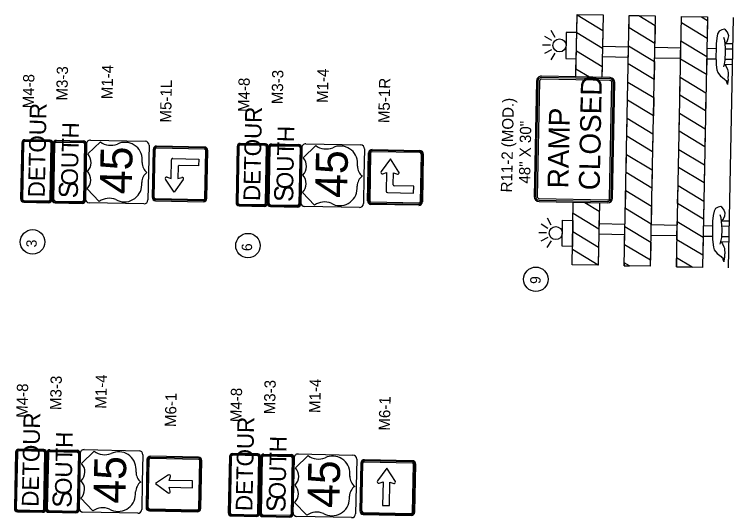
# Model space of a CAD drawing. Extents: x 335726 to 369746, y 119154 to 200788.
# Drawn here: x 339293 to 349629, y 178618 to 185853 of the extents above; entities that cross this region are included whole.
import ezdxf

# ---------------------------------------------------------------- set-up
doc = ezdxf.new("R2010")
doc.units = 0
doc.layers.add('CA-TEXT', color=7, linetype='Continuous')
doc.layers.add('P_SGN_Cell', color=7, linetype='Continuous')

msp = doc.modelspace()

# ---------------------------------------------------------------- linework, layer by layer
at = {"layer": 'CA-TEXT'}
for centre in [(339554, 182582), (342650, 182529), (346787, 182044)]:
    msp.add_circle(centre, 176, dxfattribs=at)
at = {"layer": 'P_SGN_Cell'}
for p, q in [((349557, 182209), (349629, 185808)), ((347015, 185476), (346918, 185535)), ((347064, 185523), (347009, 185622)), ((349506, 185436), (349622, 185433)), ((346996, 185411), (346883, 185413)), ((347012, 185345), (346913, 185291)), ((347746, 185396), (348120, 185388)), ((348495, 185381), (348870, 185373)), ((349245, 185366), (349378, 185363)), ((349511, 185360), (349620, 185358)), ((347059, 185296), (347001, 185200)), ((347743, 185246), (348117, 185238)), ((348492, 185231), (348867, 185223)), ((349242, 185216), (349375, 185213)), ((349497, 185136), (349616, 185133)), ((349510, 185210), (349617, 185208)), ((347853, 184902), (346868, 184922)), ((347854, 184944), (346869, 184964)), ((347853, 184925), (346869, 184945)), ((346798, 184895), (346764, 183235)), ((346816, 184895), (346783, 183235)), ((346840, 184894), (346806, 183235)), ((347847, 183214), (347881, 184873)), ((347871, 183213), (347904, 184873)), ((347889, 183213), (347923, 184872)), ((339833, 183189), (339849, 184000)), ((339844, 183190), (339860, 184000)), ((339859, 183189), (339875, 183999)), ((339894, 184018), (340284, 184010)), ((339895, 184044), (340285, 184036)), ((339895, 184033), (340285, 184025)), ((340303, 183991), (340286, 183181)), ((340318, 183990), (340301, 183181)), ((340329, 183990), (340313, 183180)), ((340313, 183203), (340329, 183990)), ((340529, 184021), (340347, 183846)), ((340386, 184045), (341174, 184029)), ((342990, 183991), (343380, 183983)), ((343481, 183992), (344269, 183976)), ((341229, 183972), (341221, 183578)), ((341229, 183972), (341229, 183972)), ((341286, 183912), (341273, 183223)), ((341286, 183223), (341300, 183912)), ((341302, 183222), (341316, 183911)), ((342025, 183933), (341336, 183947)), ((342025, 183917), (341336, 183930)), ((342026, 183946), (341337, 183960)), ((342030, 183208), (342044, 183897)), ((342047, 183207), (342061, 183896)), ((342060, 183207), (342074, 183896)), ((342928, 183136), (342944, 183947)), ((342939, 183137), (342955, 183947)), ((342954, 183136), (342970, 183946)), ((342989, 183965), (343379, 183957)), ((342990, 183980), (343380, 183972)), ((343398, 183938), (343381, 183128)), ((343413, 183937), (343396, 183128)), ((343424, 183937), (343408, 183127)), ((343408, 183150), (343424, 183937)), ((343624, 183968), (343442, 183793)), ((344324, 183919), (344316, 183525)), ((344324, 183919), (344324, 183919)), ((344433, 183909), (345122, 183895)), ((345122, 183882), (344433, 183896)), ((341569, 183781), (341943, 183774)), ((344369, 183172), (344383, 183861)), ((344396, 183861), (344382, 183172)), ((344412, 183860), (344399, 183171)), ((345121, 183866), (344433, 183879)), ((345141, 183846), (345127, 183157)), ((345157, 183845), (345143, 183156)), ((345170, 183845), (345156, 183156)), ((341130, 183723), (341131, 183759)), ((341544, 183495), (341549, 183762)), ((341941, 183675), (341662, 183681)), ((341943, 183774), (341941, 183675)), ((344226, 183670), (344226, 183706)), ((344696, 183776), (344565, 183593)), ((344820, 183587), (344696, 183776)), ((341221, 183578), (341213, 183185)), ((341646, 183665), (341642, 183493)), ((344586, 183562), (344643, 183578)), ((344643, 183578), (344638, 183311)), ((344738, 183404), (344742, 183576)), ((344742, 183576), (344798, 183558)), ((341589, 183295), (341465, 183484)), ((341488, 183513), (341544, 183495)), ((341721, 183478), (341589, 183295)), ((341642, 183493), (341699, 183509)), ((344316, 183525), (344308, 183132)), ((341124, 183402), (341125, 183437)), ((344219, 183349), (344220, 183384)), ((345033, 183382), (344754, 183387)), ((345031, 183283), (345033, 183382)), ((340337, 183346), (340512, 183164)), ((343432, 183293), (343607, 183111)), ((344657, 183291), (345031, 183283)), ((339877, 183170), (340267, 183162)), ((342010, 183188), (341321, 183202)), ((342010, 183172), (341321, 183186)), ((341321, 183173), (342010, 183159)), ((346833, 183182), (347818, 183163)), ((346833, 183164), (347818, 183144)), ((346834, 183206), (347818, 183186)), ((339877, 183155), (340267, 183147)), ((339877, 183144), (340267, 183136)), ((341155, 183130), (340368, 183145)), ((342972, 183117), (343362, 183109)), ((342972, 183102), (343362, 183094)), ((342972, 183091), (343362, 183083)), ((344251, 183077), (343463, 183092)), ((345106, 183108), (344417, 183122)), ((345107, 183137), (344418, 183151)), ((345106, 183121), (344418, 183135)), ((347009, 182824), (346955, 182923)), ((347694, 182847), (348069, 182839)), ((349454, 182886), (349570, 182884)), ((346960, 182777), (346864, 182835)), ((348444, 182831), (348819, 182824)), ((349194, 182816), (349323, 182814)), ((349461, 182811), (349569, 182809)), ((346941, 182712), (346829, 182714)), ((346958, 182646), (346859, 182591)), ((347691, 182697), (348066, 182689)), ((348441, 182681), (348816, 182674)), ((349191, 182666), (349323, 182664)), ((349458, 182661), (349566, 182659)), ((347005, 182597), (346946, 182500)), ((349446, 182586), (349564, 182584)), ((339743, 178739), (339759, 179550)), ((339754, 178740), (339771, 179550)), ((339769, 178739), (339786, 179549)), ((339805, 179594), (340195, 179586)), ((339805, 179583), (340195, 179575)), ((339805, 179568), (340195, 179560)), ((340213, 179541), (340197, 178731)), ((340228, 179540), (340212, 178731)), ((340239, 179540), (340223, 178730)), ((340223, 178753), (340239, 179540)), ((340439, 179571), (340257, 179396)), ((340297, 179595), (341084, 179579)), ((341139, 179522), (341131, 179128)), ((341139, 179522), (341139, 179522)), ((341198, 179454), (341185, 178765)), ((341198, 178765), (341212, 179454)), ((341214, 178764), (341228, 179453)), ((341248, 179489), (341937, 179475)), ((341248, 179473), (341937, 179459)), ((341938, 179488), (341249, 179502)), ((341942, 178750), (341956, 179439)), ((341959, 178749), (341973, 179438)), ((341972, 178749), (341986, 179438)), ((342817, 178677), (342834, 179488)), ((342829, 178678), (342845, 179488)), ((342844, 178678), (342860, 179487)), ((342879, 179532), (343269, 179524)), ((342879, 179521), (343269, 179513)), ((342879, 179506), (343269, 179498)), ((343287, 179479), (343271, 178669)), ((343302, 179478), (343286, 178669)), ((343313, 179478), (343297, 178668)), ((343298, 178691), (343313, 179478)), ((343514, 179509), (343332, 179334)), ((343371, 179533), (344158, 179517)), ((344213, 179460), (344205, 179066)), ((344213, 179460), (344213, 179460)), ((344322, 179437), (345011, 179423)), ((345012, 179436), (344323, 179450)), ((344272, 179402), (344259, 178713)), ((344272, 178713), (344286, 179402)), ((344288, 178712), (344302, 179401)), ((344322, 179421), (345011, 179407)), ((345016, 178698), (345030, 179387)), ((345033, 178697), (345047, 179386)), ((345046, 178697), (345060, 179386)), ((341041, 179273), (341042, 179309)), ((341508, 179231), (341320, 179107)), ((344115, 179211), (344116, 179247)), ((344644, 179328), (344512, 179145)), ((344768, 179139), (344644, 179328)), ((341131, 179128), (341123, 178735)), ((341519, 179152), (341537, 179208)), ((341855, 179145), (341519, 179152)), ((341853, 179047), (341855, 179145)), ((344534, 179114), (344591, 179130)), ((344591, 179130), (344584, 178794)), ((344682, 178792), (344689, 179128)), ((344689, 179128), (344745, 179110)), ((341320, 179107), (341503, 178975)), ((341533, 178997), (341517, 179054)), ((341517, 179054), (341853, 179047)), ((344205, 179066), (344197, 178673)), ((341034, 178952), (341035, 178987)), ((344109, 178890), (344109, 178925)), ((340247, 178896), (340422, 178714)), ((343321, 178834), (343496, 178652)), ((339788, 178720), (340178, 178712)), ((341233, 178744), (341922, 178730)), ((341233, 178728), (341922, 178714)), ((341233, 178715), (341922, 178701)), ((344584, 178794), (344682, 178792)), ((339787, 178705), (340177, 178697)), ((339787, 178694), (340177, 178686)), ((341066, 178680), (340278, 178695)), ((342861, 178632), (343251, 178624)), ((342862, 178658), (343252, 178651)), ((342862, 178643), (343251, 178636)), ((344140, 178618), (343353, 178634)), ((344307, 178692), (344996, 178678)), ((344307, 178676), (344996, 178662)), ((344307, 178663), (344996, 178649))]:
    msp.add_line(p, q, dxfattribs=at)
for points in [[(347362, 184954), (347380, 185853), (347755, 185846), (347737, 184946)], [(349510, 185443), (349538, 185463), (349552, 185507), (349560, 185545), (349540, 185597), (349514, 185631), (349498, 185642), (349459, 185632), (349422, 185613), (349400, 185572), (349386, 185511), (349379, 185429), (349378, 185353), (349376, 185250), (349379, 185168), (349380, 185127), (349390, 185055), (349403, 185017), (349443, 184965), (349463, 184951), (349504, 184919), (349513, 184909), (349540, 184891)], [(349497, 185138), (349509, 185196), (349514, 185313), (349513, 185371), (349501, 185477), (349488, 185519)], [(347559, 184950), (347364, 185068), (347369, 185328), (347740, 185104), (347737, 184946)], [(349489, 185098), (349497, 185137)], [(349508, 185128), (349521, 185104), (349541, 185062), (349547, 185042), (349549, 185011), (349553, 184980), (349553, 184963), (349548, 184952), (349551, 184901), (349547, 184901), (349544, 184891), (349539, 184847)], [(347737, 184946), (347362, 184954)], [(347737, 184946), (347559, 184950)], [(339399, 184008), (339383, 183198)], [(339410, 184008), (339394, 183198)], [(339425, 184008), (339409, 183198)], [(339804, 184019), (339444, 184026)], [(339805, 184045), (339445, 184052)], [(339805, 184034), (339445, 184041)], [(339806, 183190), (339823, 184000)], [(339821, 183190), (339838, 183999)], [(339833, 183189), (339849, 183999)], [(342900, 183992), (342540, 183999)], [(342900, 183981), (342540, 183988)], [(342494, 183955), (342478, 183145)], [(342505, 183955), (342489, 183145)], [(342520, 183955), (342504, 183145)], [(342899, 183966), (342540, 183973)], [(342902, 183137), (342918, 183947)], [(342917, 183137), (342933, 183946)], [(342928, 183136), (342944, 183946)], [(339427, 183179), (339787, 183172)], [(339427, 183164), (339787, 183157)], [(339427, 183153), (339787, 183145)], [(342522, 183126), (342882, 183119)], [(342522, 183111), (342882, 183104)], [(342522, 183100), (342882, 183092)], [(347700, 183146), (347682, 182247), (347307, 182254), (347325, 183154)], [(347492, 183150), (347698, 183026), (347693, 182766), (347322, 182990), (347325, 183154)], [(347325, 183154), (347700, 183146)], [(347325, 183154), (347492, 183150)], [(349458, 182894), (349486, 182914), (349501, 182958), (349508, 182995), (349489, 183047), (349462, 183082), (349446, 183092), (349407, 183083), (349370, 183063), (349349, 183022), (349334, 182961), (349328, 182879), (349326, 182804), (349324, 182701), (349327, 182619), (349329, 182578), (349339, 182506), (349352, 182468), (349392, 182415), (349412, 182401), (349452, 182370), (349461, 182359), (349488, 182342)], [(349446, 182589), (349458, 182647), (349463, 182763), (349461, 182822), (349450, 182928), (349437, 182969)], [(349438, 182548), (349446, 182587)], [(349457, 182578), (349470, 182554), (349490, 182513), (349496, 182492), (349498, 182461), (349502, 182430), (349501, 182413), (349496, 182403), (349500, 182352), (349495, 182352), (349493, 182341), (349487, 182297)], [(339309, 179558), (339293, 178748)], [(339321, 179558), (339304, 178748)], [(339336, 179558), (339319, 178748)], [(339715, 179595), (339355, 179602)], [(339715, 179584), (339355, 179591)], [(339715, 179569), (339355, 179576)], [(339717, 178740), (339733, 179550)], [(339732, 178740), (339748, 179549)], [(339743, 178739), (339759, 179549)], [(342789, 179533), (342430, 179540)], [(342384, 179496), (342367, 178687)], [(342395, 179496), (342379, 178686)], [(342410, 179496), (342394, 178686)], [(342789, 179522), (342429, 179529)], [(342789, 179507), (342429, 179514)], [(342791, 178678), (342807, 179488)], [(342806, 178678), (342822, 179488)], [(342817, 178677), (342834, 179487)], [(339337, 178714), (339697, 178707)], [(339338, 178729), (339698, 178722)], [(339337, 178703), (339697, 178695)], [(342411, 178641), (342771, 178633)], [(342412, 178667), (342772, 178660)], [(342412, 178652), (342772, 178645)]]:
    msp.add_lwpolyline(points, dxfattribs=at)
for points in [[(347745, 185364), (347374, 185588), (347380, 185847), (347750, 185623)], [(348057, 182239), (348130, 185838), (348504, 185831), (348432, 182232)], [(348497, 185435), (348126, 185659), (348130, 185838), (348269, 185836), (348502, 185695)], [(348807, 182224), (348879, 185823), (349254, 185816), (349182, 182216)], [(349253, 185766), (349248, 185507), (348878, 185731), (348879, 185823), (349169, 185817)], [(347224, 185594), (347217, 185219), (347367, 185216), (347374, 185591)], [(349238, 184987), (348867, 185211), (348872, 185471), (349243, 185247)], [(348486, 184916), (348115, 185140), (348121, 185399), (348491, 185175)], [(349227, 184468), (348857, 184692), (348862, 184951), (349232, 184727)], [(348476, 184396), (348105, 184620), (348110, 184880), (348481, 184656)], [(349217, 183948), (348846, 184172), (348851, 184432), (349222, 184208)], [(348465, 183877), (348095, 184101), (348100, 184360), (348470, 184136)], [(349206, 183429), (348836, 183653), (348841, 183912), (349211, 183688)], [(348455, 183357), (348084, 183581), (348089, 183841), (348460, 183617)], [(349196, 182909), (348825, 183133), (348830, 183393), (349201, 183169)], [(348444, 182838), (348074, 183062), (348079, 183321), (348449, 183097)], [(347163, 182520), (347170, 182895), (347320, 182892), (347312, 182517)], [(349185, 182390), (348815, 182614), (348820, 182873), (349191, 182649)], [(348434, 182318), (348063, 182542), (348068, 182802), (348439, 182578)], [(347682, 182247), (347312, 182471), (347317, 182730), (347687, 182506)], [(348810, 182354), (348807, 182224), (349032, 182219)], [(348058, 182282), (348057, 182239), (348132, 182238)]]:
    msp.add_lwpolyline(points, close=True, dxfattribs=at)
for centre in [(347127, 185408), (347073, 182709)]:
    msp.add_circle(centre, 93.8, dxfattribs=at)
for centre, radius, start, end in [((346868, 184894), 70.3, 88.8462, 178.8462), ((346868, 184894), 51.6, 88.8462, 178.8462), ((346868, 184894), 28.1, 88.8462, 178.8462), ((347852, 184874), 51.6, 358.8462, 88.8462), ((347852, 184874), 70.3, 358.8462, 88.8462), ((347852, 184874), 28.1, 358.8462, 88.8462), ((339444, 184007), 45, 88.8468, 178.8468), ((339444, 184007), 33.7, 88.8468, 178.8468), ((339444, 184007), 18.7, 88.8468, 178.8468), ((339804, 184000), 18.7, 358.8468, 88.8468), ((339804, 184000), 45, 358.8468, 88.8468), ((339804, 184000), 33.7, 358.8468, 88.8468), ((339894, 183999), 45, 88.8462, 178.8462), ((339894, 183999), 33.7, 88.8462, 178.8462), ((339894, 183999), 18.7, 88.8462, 178.8462), ((340284, 183991), 18.7, 358.8462, 88.8462), ((340284, 183991), 45, 358.8462, 88.8462), ((340284, 183991), 33.7, 358.8462, 88.8462), ((340385, 183989), 56.2, 88.8462, 178.8462), ((340679, 184221), 250, 233.1143, 291.9873), ((340881, 183764), 250, 358.8462, 115.6928), ((341172, 183973), 56.2, 358.8462, 88.8462), ((342539, 183954), 45, 88.8468, 178.8468), ((342539, 183954), 33.7, 88.8468, 178.8468), ((342899, 183947), 45, 358.8468, 88.8468), ((342989, 183946), 45, 88.8462, 178.8462), ((343480, 183936), 56.2, 88.8462, 178.8462), ((341336, 183911), 49.2, 88.8462, 178.8462), ((341336, 183911), 36.1, 88.8462, 178.8462), ((341336, 183911), 19.7, 88.8462, 178.8462), ((342025, 183897), 36.1, 358.8462, 88.8462), ((342025, 183897), 19.7, 358.8462, 88.8462), ((342025, 183897), 49.2, 358.8462, 88.8462), ((342539, 183954), 18.7, 88.8468, 178.8468), ((342899, 183947), 18.7, 358.8468, 88.8468), ((342899, 183947), 33.7, 358.8468, 88.8468), ((342989, 183946), 33.7, 88.8462, 178.8462), ((342989, 183946), 18.7, 88.8462, 178.8462), ((343379, 183938), 18.7, 358.8462, 88.8462), ((343379, 183938), 45, 358.8462, 88.8462), ((343379, 183938), 33.7, 358.8462, 88.8462), ((343774, 184168), 250, 233.1143, 291.9873), ((343976, 183711), 250, 358.8462, 115.6928), ((344268, 183920), 56.2, 358.8462, 88.8462), ((344432, 183860), 49.2, 88.8462, 178.8462), ((344432, 183860), 36.1, 88.8462, 178.8462), ((345121, 183846), 49.2, 358.8462, 88.8462), ((345121, 183846), 36.1, 358.8462, 88.8462), ((340217, 183724), 179, 314.4191, 43.2734), ((341569, 183762), 19.7, 88.8462, 178.8462), ((343312, 183671), 179, 314.4191, 43.2734), ((344432, 183860), 19.7, 88.8462, 178.8462), ((345121, 183846), 19.7, 358.8462, 88.8462), ((341311, 183721), 181, 179.1885, 231.634), ((341662, 183665), 16.4, 88.8462, 178.8462), ((340212, 183474), 179, 314.4191, 43.2734), ((341305, 183433), 181, 126.0584, 178.5039), ((344406, 183668), 181, 179.1885, 231.634), ((344581, 183581), 19.7, 144.3166, 285.6488), ((344804, 183577), 19.7, 252.0436, 33.3759), ((341481, 183494), 19.7, 72.0436, 213.3759), ((341705, 183490), 19.7, 324.3166, 105.6488), ((343307, 183421), 179, 314.4191, 43.2734), ((344400, 183380), 181, 126.0584, 178.5039), ((340874, 183407), 250, 240.0981, 358.8463), ((344754, 183404), 16.4, 178.8462, 268.8462), ((343969, 183354), 250, 240.0981, 358.8463), ((344657, 183310), 19.7, 178.8462, 268.8462), ((339428, 183198), 45, 178.8468, 268.8468), ((339428, 183198), 33.7, 178.8468, 268.8468), ((339428, 183198), 18.7, 178.8468, 268.8468), ((339428, 183198), 18.7, 178.8468, 186.1883), ((339788, 183190), 33.7, 268.8468, 358.8468), ((339788, 183190), 18.7, 268.8468, 358.8468), ((339788, 183190), 45, 268.8468, 358.8468), ((339878, 183189), 45, 179.6119, 268.8462), ((339878, 183189), 33.7, 178.8462, 268.8462), ((339878, 183189), 18.7, 178.8462, 268.8462), ((340268, 183181), 33.7, 268.8462, 358.8462), ((340268, 183181), 18.7, 268.8462, 358.8462), ((340268, 183181), 45, 268.8462, 358.8462), ((340369, 183202), 56.2, 178.8462, 268.8462), ((340655, 182959), 250, 67.7159, 124.7982), ((341157, 183186), 56.2, 268.8462, 358.8462), ((341322, 183222), 49.2, 178.8462, 268.8462), ((341322, 183222), 36.1, 178.8462, 268.8462), ((341322, 183222), 19.7, 178.8462, 268.8462), ((342011, 183208), 19.7, 268.8462, 358.8462), ((342011, 183208), 36.1, 268.8462, 358.8462), ((342011, 183208), 49.2, 268.8462, 358.8462), ((344418, 183171), 49.2, 178.8462, 268.8462), ((344418, 183171), 36.1, 178.8462, 268.8462), ((344418, 183171), 19.7, 178.8462, 268.8462), ((345107, 183157), 19.7, 268.8462, 358.8462), ((346834, 183234), 70.3, 178.8462, 268.8462), ((346834, 183234), 51.6, 178.8462, 268.8462), ((346834, 183234), 28.1, 178.8462, 269.9241), ((347819, 183214), 28.1, 268.8462, 358.8462), ((347819, 183214), 70.3, 268.8462, 358.8462), ((347819, 183214), 51.6, 268.8462, 358.8462), ((342523, 183145), 45, 178.8468, 268.8468), ((342523, 183145), 33.7, 178.8468, 268.8468), ((342523, 183145), 18.7, 178.8468, 268.8468), ((342523, 183145), 18.7, 178.8468, 186.1883), ((342883, 183137), 33.7, 268.8468, 358.8468), ((342883, 183137), 18.7, 268.8468, 358.8468), ((342883, 183137), 45, 268.8468, 358.8468), ((342973, 183136), 45, 179.6119, 268.8462), ((342973, 183136), 33.7, 178.8462, 268.8462), ((342973, 183136), 18.7, 178.8462, 268.8462), ((343363, 183128), 33.7, 268.8462, 358.8462), ((343363, 183128), 18.7, 268.8462, 358.8462), ((343363, 183128), 45, 268.8462, 358.8462), ((343464, 183149), 56.2, 178.8462, 268.8462), ((343750, 182906), 250, 67.7159, 124.7982), ((344252, 183133), 56.2, 268.8462, 358.8462), ((345107, 183157), 36.1, 268.8462, 358.8462), ((345107, 183157), 49.2, 268.8462, 358.8462), ((339354, 179557), 45, 88.8468, 178.8468), ((339354, 179557), 33.7, 88.8468, 178.8468), ((339354, 179557), 18.7, 88.8468, 178.8468), ((339714, 179550), 45, 358.8468, 88.8468), ((339714, 179550), 33.7, 358.8468, 88.8468), ((339714, 179550), 18.7, 358.8468, 88.8468), ((339804, 179549), 45, 88.8462, 178.8462), ((339804, 179549), 33.7, 88.8462, 178.8462), ((339804, 179549), 18.7, 88.8462, 178.8462), ((340194, 179541), 45, 358.8462, 88.8462), ((340194, 179541), 33.7, 358.8462, 88.8462), ((340194, 179541), 18.7, 358.8462, 88.8462), ((340295, 179539), 56.2, 88.8462, 178.8462), ((340590, 179771), 250, 233.1143, 291.9873), ((340792, 179314), 250, 358.8462, 115.6928), ((341083, 179523), 56.2, 358.8462, 88.8462), ((342429, 179495), 45, 88.8468, 178.8468), ((341248, 179453), 49.2, 88.8468, 178.8468), ((341248, 179453), 49.2, 149.4503, 178.8468), ((341248, 179453), 36.1, 88.8468, 178.8468), ((341248, 179453), 19.7, 88.8468, 178.8468), ((341937, 179439), 36.1, 358.8468, 88.8468), ((341937, 179439), 19.7, 358.8468, 88.8468), ((341937, 179439), 49.2, 358.8468, 88.8468), ((342429, 179495), 33.7, 88.8468, 178.8468), ((342429, 179495), 18.7, 88.8468, 178.8468), ((342789, 179488), 45, 358.8468, 88.8468), ((342789, 179488), 33.7, 358.8468, 88.8468), ((342789, 179488), 18.7, 358.8468, 88.8468), ((342879, 179487), 45, 88.8462, 178.8462), ((342879, 179487), 33.7, 88.8462, 178.8462), ((342879, 179487), 18.7, 88.8462, 178.8462), ((343268, 179479), 45, 358.8462, 88.8462), ((343268, 179479), 33.7, 358.8462, 88.8462), ((343268, 179479), 18.7, 358.8462, 88.8462), ((343370, 179477), 56.2, 88.8462, 178.8462), ((343664, 179709), 250, 233.1143, 291.9873), ((343866, 179252), 250, 358.8462, 115.6928), ((344157, 179461), 56.2, 358.8462, 88.8462), ((344322, 179401), 49.2, 88.8468, 178.8468), ((344322, 179401), 36.1, 88.8468, 178.8468), ((345011, 179387), 49.2, 358.8468, 88.8468), ((340127, 179274), 179, 314.4191, 43.2734), ((343201, 179212), 179, 314.4191, 43.2734), ((344322, 179401), 49.2, 149.4503, 178.8468), ((344322, 179401), 19.7, 88.8468, 178.8468), ((345011, 179387), 36.1, 358.8468, 88.8468), ((345011, 179387), 19.7, 358.8468, 88.8468), ((341222, 179271), 181, 179.1885, 231.634), ((341519, 179214), 19.7, 342.0442, 123.3765), ((340122, 179024), 179, 314.4191, 43.2734), ((341216, 178983), 181, 126.0584, 178.5039), ((344296, 179209), 181, 179.1885, 231.634), ((344528, 179133), 19.7, 144.3172, 285.6494), ((344751, 179129), 19.7, 252.0442, 33.3765), ((343196, 178962), 179, 314.4191, 43.2734), ((344290, 178921), 181, 126.0584, 178.5039), ((340784, 178957), 250, 240.0981, 358.8463), ((341514, 178991), 19.7, 234.3172, 15.6494), ((343859, 178895), 250, 240.0981, 358.8463), ((339338, 178748), 45, 178.8468, 268.8468), ((339338, 178748), 33.7, 178.8468, 268.8468), ((339338, 178748), 18.7, 178.8468, 268.8468), ((339338, 178748), 18.7, 178.8468, 186.1883), ((339698, 178740), 33.7, 268.8468, 358.8468), ((339698, 178740), 45, 268.8468, 358.8468), ((339698, 178740), 18.7, 268.8468, 358.8468), ((339788, 178739), 45, 179.6119, 268.8462), ((339788, 178739), 33.7, 178.8462, 268.8462), ((339788, 178739), 18.7, 178.8462, 268.8462), ((340178, 178731), 33.7, 268.8462, 358.8462), ((340178, 178731), 45, 268.8462, 358.8462), ((340178, 178731), 18.7, 268.8462, 358.8462), ((340280, 178752), 56.2, 178.8462, 268.8462), ((340565, 178509), 250, 67.7159, 124.7982), ((341067, 178736), 56.2, 268.8462, 358.8462), ((341234, 178764), 49.2, 178.8468, 268.8468), ((341234, 178764), 36.1, 178.8468, 268.8468), ((341234, 178764), 19.7, 178.8468, 268.8468), ((341923, 178750), 19.7, 268.8468, 358.8468), ((341923, 178750), 36.1, 268.8468, 358.8468), ((341923, 178750), 49.2, 268.8468, 358.8468), ((344308, 178712), 49.2, 178.8468, 268.8468), ((344308, 178712), 36.1, 178.8468, 268.8468), ((344308, 178712), 19.7, 178.8468, 268.8468), ((342412, 178686), 45, 178.8468, 268.8468), ((342412, 178686), 33.7, 178.8468, 268.8468), ((342412, 178686), 18.7, 178.8468, 268.8468), ((342412, 178686), 18.7, 178.8468, 186.1883), ((342772, 178678), 45, 268.8468, 358.8468), ((342772, 178678), 33.7, 268.8468, 358.8468), ((342772, 178678), 18.7, 268.8468, 358.8468), ((342862, 178677), 45, 179.6119, 268.8462), ((342862, 178677), 33.7, 178.8462, 268.8462), ((342862, 178677), 18.7, 178.8462, 268.8462), ((343252, 178669), 33.7, 268.8462, 358.8462), ((343252, 178669), 45, 268.8462, 358.8462), ((343252, 178669), 18.7, 268.8462, 358.8462), ((343354, 178690), 56.2, 178.8462, 268.8462), ((343639, 178447), 250, 67.7159, 124.7982), ((344141, 178674), 56.2, 268.8462, 358.8462), ((344997, 178698), 19.7, 268.8468, 358.8468), ((344997, 178698), 36.1, 268.8468, 358.8468), ((344997, 178698), 49.2, 268.8468, 358.8468)]:
    msp.add_arc(centre, radius, start, end, dxfattribs=at)
for points in [[(349539, 184850), (349533, 184881), (349524, 184902)], [(349488, 182300), (349481, 182331), (349473, 182352)]]:
    msp.add_spline(points, degree=3, dxfattribs=at)

# ---------------------------------------------------------------- texts
at = {"layer": 'CA-TEXT'}
for s, p in [('3', (339613, 182502)), ('6', (342708, 182449)), ('9', (346855, 181976))]:
    msp.add_text(s, height=150, rotation=88.8468, dxfattribs=at).set_placement(p)
at = {"layer": 'P_SGN_Cell'}
for s, height, rotation, p in [('M3-3', 162, 88.8462, (340055, 184613)), ('M1-4', 162, 88.8462, (340704, 184632)), ('M3-3', 162, 88.8462, (343150, 184560)), ('M1-4', 162, 88.8462, (343799, 184579)), ('M4-8', 162, 88.8468, (339572, 184501)), ('M4-8', 162, 88.8468, (342667, 184448)), ('M5-1R', 162, 88.8462, (344683, 184289)), ('CLOSED', 300, 88.8462, (347704, 183322)), ('M5-1L', 162, 88.8462, (341546, 184296)), ('R11-2 (MOD.)', 162, 88.8462, (346445, 183292)), ('DETOUR', 240, 88.8468, (339729, 183222)), ('DETOUR', 240, 88.8468, (342824, 183169)), (' RAMP ', 300, 88.8462, (347252, 183238)), ('48" X 30"', 162, 88.8462, (346705, 183419)), ('OUTH', 240, 88.8462, (340204, 183391)), ('OUTH', 240, 88.8462, (343299, 183338)), ('45', 460, 88.8462, (340979, 183265)), ('45', 460, 88.8462, (344074, 183212)), ('S', 274, 88.8462, (340204, 183207)), ('S', 274, 88.8462, (343299, 183154)), ('M3-3', 162, 88.8462, (339966, 180163)), ('M1-4', 162, 88.8462, (340615, 180182)), ('M3-3', 162, 88.8462, (343040, 180102)), ('M1-4', 162, 88.8462, (343689, 180120)), ('M4-8', 162, 88.8468, (339482, 180051)), ('M4-8', 162, 88.8468, (342557, 179989)), ('M6-1', 162, 88.8468, (341616, 179919)), ('M6-1', 162, 88.8468, (344690, 179867)), ('DETOUR', 240, 88.8468, (339639, 178772)), ('DETOUR', 240, 88.8468, (342713, 178710)), ('OUTH', 240, 88.8462, (340115, 178941)), ('OUTH', 240, 88.8462, (343189, 178879)), ('45', 460, 88.8462, (340889, 178815)), ('45', 460, 88.8462, (343963, 178753)), ('S', 274, 88.8462, (340114, 178757)), ('S', 274, 88.8462, (343188, 178695))]:
    msp.add_text(s, height=height, rotation=rotation, dxfattribs=at).set_placement(p)

doc.saveas('drawing.dxf')
